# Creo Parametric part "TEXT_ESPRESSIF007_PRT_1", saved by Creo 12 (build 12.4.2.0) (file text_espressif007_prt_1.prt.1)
Units: Custom; MM, KILOGRAM, SECS

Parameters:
  PTC_WM_ITERATION = "0"
  PTC_WM_VERSION = "-.0"
  PTC_WM_LIFECYCLE_STATE = "In Work"
  PTC_WM_LIFECYCLE = "MO_CADDocument"
  PTC_WM_CREATED_BY = "Maximilian Roepper (Z0017RMS: MO)"
  PTC_WM_CREATED_ON = "18-Sep-26 11:36:42 AM"
  PTC_WM_MODIFIED_BY = "Maximilian Roepper (Z0017RMS: MO)"
  PTC_WM_MODIFIED_ON = "18-Sep-26 11:36:46 AM"
  PDMLINKNUMBER = "PDM000071455029"
  PTC_WM_NAME = "text_espressif007_prt_1.prt"
  PTC_WM_NUMBER = "PDM000071455029"

Other parameters: WEIGHT, WEIGHT_FACTOR, WEIGHT_ADD, _MASS_TEMP, _DIFF_TEMP, MC_ERRORS, SUPPLIER

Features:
  1. coordinate system
  2. datum plane "PRT_YZ"
  3. datum plane "PRT_XY"
  4. datum plane "PRT_XZ"
  5. coordinate system
  6. datum axis
  7. datum axis
  8. datum axis
  9. coordinate system
  10. imported feature
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
Other named items: PRT, SIEMENS_MO, DRW_VIEW_ORG, PRT_X, PRT_Y, PRT_Z, CS0, ROUGH_GROB

Layers: 00_STD_CSYS-KSYS, 01_STD_PLANES-EBENEN, 02_STD_AXES-ACHSEN, 03_STD_CSYS-KSYS, 24_IMPORT_FEAT-IMPORT_KE

Surfaces: 6 plane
